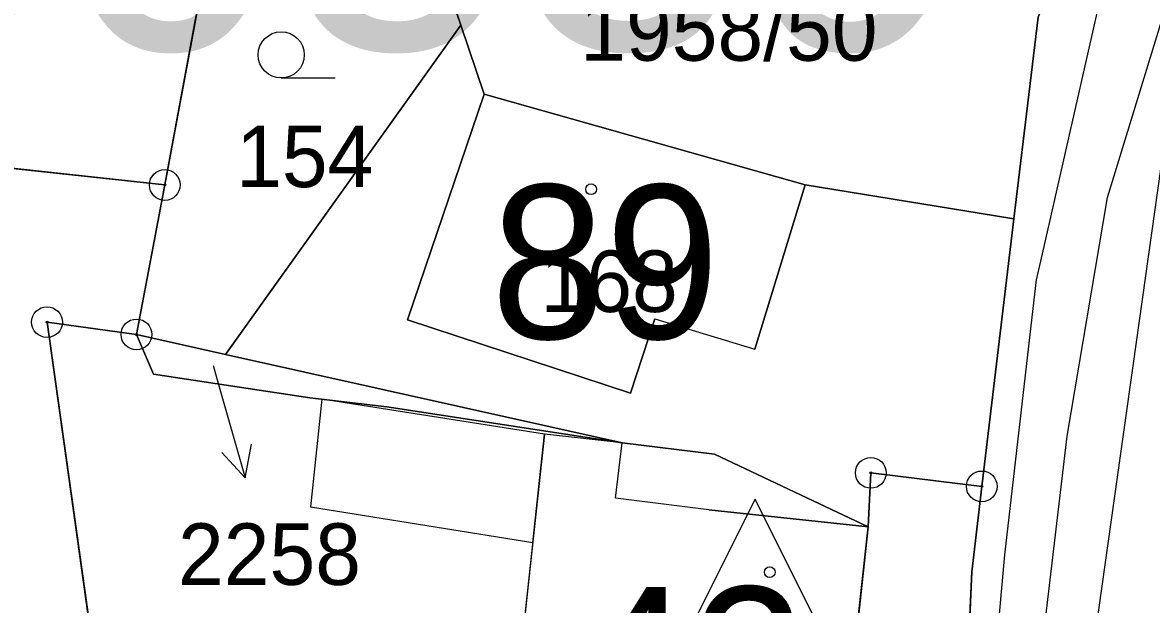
# Model space of a CAD drawing. Extents: x -706130 to -698555, y -971544 to -967260.
# Drawn here: x -704408.64 to -704371.94, y -970301.16 to -970282.24 of the extents above; entities that cross this region are included whole.
import ezdxf

# ---------------------------------------------------------------- set-up
doc = ezdxf.new("R2010")
doc.units = 0
for name, color, linetype in [('_Doplněk budov pro zastavěnost', 7, 'Continuous'), ('Architektonicky cenná stavba S', 7, 'Continuous'), ('BPEJ I-II trida ochrany S', 7, 'Continuous'), ('Docházková izochrona - BUS S', 7, 'Continuous'), ('Docházková izochrona - VLAK N', 7, 'Continuous'), ('KN_Budovy', 7, 'Continuous'), ('KN_Budovy_cisla_domovni', 7, 'Continuous'), ('KN_Hranice_parcel', 7, 'Continuous'), ('KN_Hranice_parcel_vnitrni_kresba', 7, 'Continuous'), ('KN_Parcelni cisla', 7, 'Continuous'), ('KN_Parcelni cisla_sipky', 7, 'Continuous'), ('KN_Polygon parcely', 7, 'Continuous'), ('KN_POZEMKY_13_ZASTAVENA PLOCHA', 7, 'Continuous'), ('KN_POZEMKY_14_OSTATNI PLOCHA', 7, 'Continuous'), ('KN_POZEMKY_5_ZAHRADA', 7, 'Continuous'), ('KN_POZEMKY_7_TTP', 7, 'Continuous'), ('KN_VYUZITI_16_ostatni plocha_silnice', 7, 'Continuous'), ('KN_VYUZITI_17_ostatni plocha_ostatni komunikace', 7, 'Continuous'), ('KN_VYUZITI_26_ostatni plocha_jina plocha', 7, 'Continuous'), ('KN_Značky bodu BP', 7, 'Continuous'), ('KN_Značky budov', 7, 'Continuous'), ('KN_Značky kultur', 7, 'Continuous'), ('Komunikace III třídy osy S', 7, 'Continuous'), ('Nemovité kulturní památky popis', 7, 'Continuous'), ('Nemovité kulturní památky S', 7, 'Continuous'), ('Plochy doprava silniční - silnice III třídy S', 7, 'Continuous'), ('Plochy smíšené obytné venkovské S', 7, 'Continuous'), ('Plynovody STL S', 7, 'Continuous'), ('Regulační bloky zastavěné S', 7, 'Continuous'), ('Vodovodní řady - rozváděcí S', 7, 'Continuous')]:
    doc.layers.add(name, color=color, linetype=linetype)

msp = doc.modelspace()

# ---------------------------------------------------------------- linework, layer by layer
at = {"layer": '_Doplněk budov pro zastavěnost'}
msp.add_line((-704392.053, -970299.149), (-704391.67, -970295.62), dxfattribs=at)
msp.add_lwpolyline([(-704391.67, -970295.62), (-704398.912, -970294.485), (-704399.276, -970297.99), (-704392.053, -970299.149)], dxfattribs=at)
at = {"layer": 'Architektonicky cenná stavba S'}
msp.add_lwpolyline([(-704384.823, -970297.732), (-704386.823, -970301.732), (-704390.823, -970303.732), (-704386.823, -970305.732), (-704384.823, -970309.732), (-704382.823, -970305.732), (-704378.823, -970303.732), (-704382.823, -970301.732)], close=True, dxfattribs=at)
at = {"layer": 'BPEJ I-II trida ochrany S'}
for p, q in [((-704394.39, -970282.32), (-704394.9, -970280.83)), ((-704402.05, -970293.03), (-704394.39, -970282.32)), ((-704406.09, -970304.49), (-704407.85, -970291.98)), ((-704407.85, -970291.98), (-704404.94, -970292.38)), ((-704404.94, -970292.38), (-704402.05, -970293.03))]:
    msp.add_line(p, q, dxfattribs=at)
at = {"layer": 'Docházková izochrona - BUS S'}
msp.add_arc((-704361.829, -969946.93), 400, 155.51821, 17.33949, dxfattribs=at)
at = {"layer": 'Docházková izochrona - VLAK N'}
msp.add_circle((-704165.451, -969778.767), 800, dxfattribs=at)
at = {"layer": 'KN_Budovy'}
for points in [[(-704396.13, -970291.91), (-704388.88, -970294.29), (-704388.08, -970291.87), (-704384.83, -970292.86), (-704383.2, -970287.52), (-704393.63, -970284.57)], [(-704382.31, -970309.38), (-704381.15, -970298.64), (-704386.33, -970298.08), (-704389.36, -970297.7), (-704389.15, -970295.9), (-704391.67, -970295.62), (-704392.41, -970302.43), (-704387.16, -970303.14), (-704387.49, -970306.01), (-704387.24, -970306.04), (-704387.56, -970308.81)]]:
    msp.add_lwpolyline(points, close=True, dxfattribs=at)
at = {"layer": 'KN_Hranice_parcel'}
for p, q in [((-704402.69, -970280.35), (-704404.02, -970287.52)), ((-704394.39, -970282.32), (-704402.05, -970293.03)), ((-704404.02, -970287.52), (-704433.21, -970284.34)), ((-704404.02, -970287.52), (-704404.94, -970292.38)), ((-704377.45, -970297.32), (-704376.41, -970288.62)), ((-704404.94, -970292.38), (-704402.05, -970293.03)), ((-704404.39, -970293.67), (-704404.94, -970292.38)), ((-704402.05, -970293.03), (-704389.15, -970295.9)), ((-704389.15, -970295.9), (-704396.8, -970294.73))]:
    msp.add_line(p, q, dxfattribs=at)
for points in [[(-704394.39, -970282.32), (-704394.9, -970280.83), (-704402.69, -970280.35)], [(-704375.45, -970281.66), (-704375.62, -970282.06), (-704376.41, -970288.62)], [(-704376.41, -970288.62), (-704377.54, -970288.44), (-704383.2, -970287.52), (-704393.63, -970284.57), (-704394.39, -970282.32)], [(-704404.94, -970292.38), (-704407.85, -970291.98), (-704406.09, -970304.49)], [(-704396.8, -970294.73), (-704399.3, -970294.44), (-704404.39, -970293.67)], [(-704389.15, -970295.9), (-704386.14, -970296.27), (-704381.15, -970298.64)], [(-704381.15, -970298.64), (-704381.06, -970296.88), (-704377.45, -970297.32)], [(-704381.19, -970377.72), (-704380.01, -970350.84), (-704377.78, -970300.1), (-704377.45, -970297.32)], [(-704382.57, -970312.21), (-704382.31, -970309.38), (-704381.15, -970298.64)]]:
    msp.add_lwpolyline(points, dxfattribs=at)
at = {"layer": 'KN_Hranice_parcel_vnitrni_kresba'}
for p, q in [((-704396.13, -970291.91), (-704393.63, -970284.57)), ((-704383.2, -970287.52), (-704384.83, -970292.86)), ((-704388.88, -970294.29), (-704396.13, -970291.91)), ((-704388.08, -970291.87), (-704388.88, -970294.29)), ((-704388.08, -970291.87), (-704384.83, -970292.86)), ((-704391.67, -970295.62), (-704392.41, -970302.43)), ((-704389.15, -970295.9), (-704391.67, -970295.62)), ((-704389.36, -970297.7), (-704389.15, -970295.9)), ((-704386.33, -970298.08), (-704389.36, -970297.7)), ((-704386.33, -970298.08), (-704381.15, -970298.64))]:
    msp.add_line(p, q, dxfattribs=at)
at = {"layer": 'KN_Parcelni cisla_sipky'}
for p, q in [((-704402.45, -970293.39), (-704402.23, -970294.16)), ((-704402.23, -970294.16), (-704401.403, -970297.045)), ((-704401.403, -970297.045), (-704401.198, -970295.944)), ((-704401.403, -970297.045), (-704402.16, -970296.22))]:
    msp.add_line(p, q, dxfattribs=at)
at = {"layer": 'KN_Polygon parcely'}
for points in [[(-704400.41, -970268.71), (-704432.24, -970260.61), (-704433.21, -970284.34), (-704404.02, -970287.52), (-704402.69, -970280.35), (-704401.35, -970273.14)], [(-704376.68, -970281.36), (-704387.02, -970277.2), (-704389.13, -970275.76), (-704390.41, -970274.14), (-704391.42, -970273.59), (-704395.92, -970272.11), (-704395.34, -970269.55), (-704400.21, -970267.99), (-704400.41, -970268.71), (-704401.35, -970273.14), (-704402.69, -970280.35), (-704394.9, -970280.83), (-704394.39, -970282.32), (-704393.63, -970284.57), (-704383.2, -970287.52), (-704377.54, -970288.44), (-704376.41, -970288.62), (-704375.62, -970282.06), (-704375.45, -970281.66)], [(-704404.94, -970292.38), (-704402.05, -970293.03), (-704394.39, -970282.32), (-704394.9, -970280.83), (-704402.69, -970280.35), (-704404.02, -970287.52)], [(-704383.2, -970287.52), (-704393.63, -970284.57), (-704394.39, -970282.32), (-704402.05, -970293.03), (-704389.15, -970295.9), (-704386.14, -970296.27), (-704381.15, -970298.64), (-704381.06, -970296.88), (-704377.45, -970297.32), (-704376.41, -970288.62), (-704377.54, -970288.44)], [(-704434.49, -970307.92), (-704406.06, -970306.24), (-704406.09, -970304.49), (-704407.85, -970291.98), (-704404.94, -970292.38), (-704404.02, -970287.52), (-704433.21, -970284.34)], [(-704389.75, -970308.75), (-704388.56, -970311.1), (-704382.57, -970312.21), (-704382.31, -970309.38), (-704381.15, -970298.64), (-704386.14, -970296.27), (-704389.15, -970295.9), (-704396.8, -970294.73), (-704399.3, -970294.44), (-704404.39, -970293.67), (-704404.94, -970292.38), (-704407.85, -970291.98), (-704406.09, -970304.49), (-704394.63, -970305.83), (-704391.17, -970307.32)], [(-704402.05, -970293.03), (-704404.94, -970292.38), (-704404.39, -970293.67), (-704399.3, -970294.44), (-704396.8, -970294.73), (-704389.15, -970295.9)], [(-704381.19, -970377.72), (-704380.01, -970350.84), (-704377.78, -970300.1), (-704377.45, -970297.32), (-704381.06, -970296.88), (-704381.15, -970298.64), (-704382.31, -970309.38), (-704382.57, -970312.21), (-704382.15, -970324.47), (-704382.07, -970327.37), (-704381.84, -970335.31), (-704381.53, -970351.01), (-704381.54, -970369.54), (-704387.88, -970369.26), (-704388.96, -970375.85)]]:
    msp.add_lwpolyline(points, close=True, dxfattribs=at)
msp.add_lwpolyline([(-704375.62, -970282.06), (-704376.41, -970288.62), (-704377.45, -970297.32), (-704377.78, -970300.1), (-704380.01, -970350.84), (-704381.19, -970377.72), (-704372.65, -970386.41), (-704371.76, -970369.3), (-704370.91, -970352.79), (-704370.59, -970346.53), (-704370.18, -970335.17), (-704369.52, -970316.88), (-704369.23, -970310.61), (-704368.75, -970300.09), (-704366.65, -970284.79), (-704361.08, -970269.38)], dxfattribs=at)
at = {"layer": 'KN_POZEMKY_13_ZASTAVENA PLOCHA'}
for p, q in [((-704402.05, -970293.03), (-704394.39, -970282.32)), ((-704394.39, -970282.32), (-704393.63, -970284.57)), ((-704393.63, -970284.57), (-704383.2, -970287.52)), ((-704383.2, -970287.52), (-704377.54, -970288.44)), ((-704377.54, -970288.44), (-704376.41, -970288.62)), ((-704376.41, -970288.62), (-704377.45, -970297.32)), ((-704406.09, -970304.49), (-704407.85, -970291.98)), ((-704407.85, -970291.98), (-704404.94, -970292.38)), ((-704404.94, -970292.38), (-704404.39, -970293.67)), ((-704389.15, -970295.9), (-704402.05, -970293.03)), ((-704404.39, -970293.67), (-704399.3, -970294.44)), ((-704399.3, -970294.44), (-704396.8, -970294.73)), ((-704396.8, -970294.73), (-704389.15, -970295.9)), ((-704389.15, -970295.9), (-704386.14, -970296.27)), ((-704386.14, -970296.27), (-704389.15, -970295.9)), ((-704386.14, -970296.27), (-704381.15, -970298.64)), ((-704381.15, -970298.64), (-704386.14, -970296.27)), ((-704381.06, -970296.88), (-704381.15, -970298.64)), ((-704377.45, -970297.32), (-704381.06, -970296.88)), ((-704381.15, -970298.64), (-704382.31, -970309.38))]:
    msp.add_line(p, q, dxfattribs=at)
at = {"layer": 'KN_POZEMKY_14_OSTATNI PLOCHA'}
for p, q in [((-704394.39, -970282.32), (-704394.9, -970280.83)), ((-704393.63, -970284.57), (-704394.39, -970282.32)), ((-704376.41, -970288.62), (-704375.62, -970282.06)), ((-704375.62, -970282.06), (-704376.41, -970288.62)), ((-704383.2, -970287.52), (-704393.63, -970284.57)), ((-704377.54, -970288.44), (-704383.2, -970287.52)), ((-704376.41, -970288.62), (-704377.54, -970288.44)), ((-704377.45, -970297.32), (-704376.41, -970288.62)), ((-704404.39, -970293.67), (-704404.94, -970292.38)), ((-704404.94, -970292.38), (-704402.05, -970293.03)), ((-704402.05, -970293.03), (-704389.15, -970295.9)), ((-704399.3, -970294.44), (-704404.39, -970293.67)), ((-704396.8, -970294.73), (-704399.3, -970294.44)), ((-704389.15, -970295.9), (-704396.8, -970294.73)), ((-704381.15, -970298.64), (-704381.06, -970296.88)), ((-704381.06, -970296.88), (-704377.45, -970297.32)), ((-704377.78, -970300.1), (-704377.45, -970297.32)), ((-704377.45, -970297.32), (-704377.78, -970300.1)), ((-704382.31, -970309.38), (-704381.15, -970298.64)), ((-704380.01, -970350.84), (-704377.78, -970300.1)), ((-704377.78, -970300.1), (-704380.01, -970350.84))]:
    msp.add_line(p, q, dxfattribs=at)
at = {"layer": 'KN_POZEMKY_5_ZAHRADA'}
for p, q in [((-704402.69, -970280.35), (-704404.02, -970287.52)), ((-704404.02, -970287.52), (-704402.69, -970280.35)), ((-704394.9, -970280.83), (-704394.39, -970282.32)), ((-704394.39, -970282.32), (-704402.05, -970293.03)), ((-704404.02, -970287.52), (-704433.21, -970284.34)), ((-704404.94, -970292.38), (-704404.02, -970287.52)), ((-704402.05, -970293.03), (-704404.94, -970292.38))]:
    msp.add_line(p, q, dxfattribs=at)
at = {"layer": 'KN_POZEMKY_7_TTP'}
for p, q in [((-704433.21, -970284.34), (-704404.02, -970287.52)), ((-704404.02, -970287.52), (-704404.94, -970292.38)), ((-704404.94, -970292.38), (-704407.85, -970291.98)), ((-704407.85, -970291.98), (-704406.09, -970304.49))]:
    msp.add_line(p, q, dxfattribs=at)
at = {"layer": 'KN_VYUZITI_16_ostatni plocha_silnice'}
for p, q in [((-704376.41, -970288.62), (-704375.62, -970282.06)), ((-704377.45, -970297.32), (-704376.41, -970288.62)), ((-704377.78, -970300.1), (-704377.45, -970297.32)), ((-704380.01, -970350.84), (-704377.78, -970300.1))]:
    msp.add_line(p, q, dxfattribs=at)
at = {"layer": 'KN_VYUZITI_17_ostatni plocha_ostatni komunikace'}
for p, q in [((-704381.15, -970298.64), (-704381.06, -970296.88)), ((-704381.06, -970296.88), (-704377.45, -970297.32)), ((-704377.45, -970297.32), (-704377.78, -970300.1)), ((-704382.31, -970309.38), (-704381.15, -970298.64)), ((-704377.78, -970300.1), (-704380.01, -970350.84))]:
    msp.add_line(p, q, dxfattribs=at)
at = {"layer": 'KN_VYUZITI_26_ostatni plocha_jina plocha'}
for p, q in [((-704394.39, -970282.32), (-704394.9, -970280.83)), ((-704393.63, -970284.57), (-704394.39, -970282.32)), ((-704375.62, -970282.06), (-704376.41, -970288.62)), ((-704383.2, -970287.52), (-704393.63, -970284.57)), ((-704377.54, -970288.44), (-704383.2, -970287.52)), ((-704376.41, -970288.62), (-704377.54, -970288.44)), ((-704404.39, -970293.67), (-704404.94, -970292.38)), ((-704404.94, -970292.38), (-704402.05, -970293.03)), ((-704402.05, -970293.03), (-704389.15, -970295.9)), ((-704399.3, -970294.44), (-704404.39, -970293.67)), ((-704396.8, -970294.73), (-704399.3, -970294.44)), ((-704389.15, -970295.9), (-704396.8, -970294.73))]:
    msp.add_line(p, q, dxfattribs=at)
at = {"layer": 'KN_Značky bodu BP'}
for centre, radius in [((-704404.02, -970287.52), 0.5), ((-704404.02, -970287.52), 0.0303), ((-704407.85, -970291.98), 0.5), ((-704404.94, -970292.38), 0.5), ((-704407.85, -970291.98), 0.0303), ((-704404.94, -970292.38), 0.0303), ((-704381.06, -970296.88), 0.5), ((-704381.06, -970296.88), 0.0303), ((-704377.45, -970297.32), 0.5), ((-704377.45, -970297.32), 0.0303)]:
    msp.add_circle(centre, radius, dxfattribs=at)
at = {"layer": 'KN_Značky budov'}
for centre in [(-704390.157, -970287.659), (-704384.347, -970300.109)]:
    msp.add_circle(centre, 0.175, dxfattribs=at)
at = {"layer": 'KN_Značky kultur'}
msp.add_line((-704400.233, -970284.04), (-704398.483, -970284.04), dxfattribs=at)
msp.add_circle((-704400.233, -970283.29), 0.75, dxfattribs=at)
at = {"layer": 'Komunikace III třídy osy S'}
msp.add_lwpolyline([(-704330.93, -970188.51), (-704335.437, -970204.681), (-704336.48, -970208.22), (-704338.18, -970213.14), (-704340.791, -970218.395), (-704362.238, -970261.156), (-704368.668, -970276.027), (-704371.631, -970286.925), (-704374.154, -970304.881), (-704375.815, -970349.829), (-704377.52, -970379.09), (-704378.33, -970382.9), (-704379.81, -970387.16), (-704381.8, -970391.97), (-704383.72, -970396.25), (-704386.32, -970401.18), (-704392.36, -970410.73), (-704399.98, -970422.96)], dxfattribs=at)
at = {"layer": 'Nemovité kulturní památky S'}
msp.add_lwpolyline([(-704388.08, -970291.87), (-704384.83, -970292.86), (-704383.2, -970287.52), (-704393.63, -970284.57), (-704396.13, -970291.91), (-704388.88, -970294.29)], close=True, dxfattribs=at)
at = {"layer": 'Plochy doprava silniční - silnice III třídy S'}
for p, q in [((-704375.62, -970282.06), (-704376.41, -970288.62)), ((-704376.41, -970288.62), (-704377.45, -970297.32)), ((-704377.45, -970297.32), (-704377.78, -970300.1)), ((-704377.78, -970300.1), (-704380.01, -970350.84))]:
    msp.add_line(p, q, dxfattribs=at)
at = {"layer": 'Plochy smíšené obytné venkovské S'}
for p, q in [((-704376.41, -970288.62), (-704375.62, -970282.06)), ((-704377.45, -970297.32), (-704376.41, -970288.62)), ((-704377.78, -970300.1), (-704377.45, -970297.32)), ((-704380.01, -970350.84), (-704377.78, -970300.1))]:
    msp.add_line(p, q, dxfattribs=at)
at = {"layer": 'Plynovody STL S'}
msp.add_lwpolyline([(-704398.39, -970427.39), (-704384.69, -970404.86), (-704379.67, -970395.45), (-704375.66, -970385.74), (-704373.212, -970374.188), (-704372.471, -970359.213), (-704372.11, -970351.39), (-704379.05, -970351.42), (-704379.051, -970351.17), (-704378.94, -970349.71), (-704378.15, -970320.65), (-704377.62, -970309.79), (-704376.7, -970299.55), (-704375.786, -970291.541), (-704375.67, -970290.6), (-704375.535, -970290.001), (-704372.96, -970278.67)], dxfattribs=at)
at = {"layer": 'Regulační bloky zastavěné S'}
for p, q in [((-704376.41, -970288.62), (-704375.62, -970282.06)), ((-704375.62, -970282.06), (-704376.41, -970288.62)), ((-704377.45, -970297.32), (-704376.41, -970288.62)), ((-704376.41, -970288.62), (-704377.45, -970297.32)), ((-704377.78, -970300.1), (-704377.45, -970297.32)), ((-704377.45, -970297.32), (-704377.78, -970300.1)), ((-704380.01, -970350.84), (-704377.78, -970300.1)), ((-704377.78, -970300.1), (-704380.01, -970350.84))]:
    msp.add_line(p, q, dxfattribs=at)
at = {"layer": 'Vodovodní řady - rozváděcí S'}
msp.add_lwpolyline([(-704404.59, -970428.41), (-704404.4, -970428.06), (-704389.04, -970403.19), (-704382.84, -970391.74), (-704379.76, -970383.48), (-704377.93, -970375.71), (-704377.64, -970372.75), (-704377.15, -970365.02), (-704376.91, -970343.31), (-704376.47, -970324.43), (-704376.46, -970319.47), (-704375.71, -970303.28), (-704375.47, -970302.37), (-704374.67, -970295.69), (-704373.36, -970287.93), (-704370.399, -970278.264)], dxfattribs=at)

# ---------------------------------------------------------------- texts
at = {"layer": 'KN_Budovy_cisla_domovni'}
for s, p in [('89', (-704393.418, -970292.519)), ('42', (-704390.613, -970305.589))]:
    msp.add_text(s, height=5, dxfattribs=at).set_placement(p)
at = {"layer": 'KN_Parcelni cisla'}
for s, p in [('1958/50', (-704390.51, -970283.48)), ('154', (-704401.7, -970287.59)), ('168', (-704391.8, -970291.65)), ('2258', (-704403.59, -970300.523))]:
    msp.add_text(s, height=2, dxfattribs=at).set_placement(p)
at = {"layer": 'Nemovité kulturní památky popis'}
msp.add_text('100539', height=10, dxfattribs=at).set_placement((-704422.407, -970283.1))

doc.saveas('drawing.dxf')
